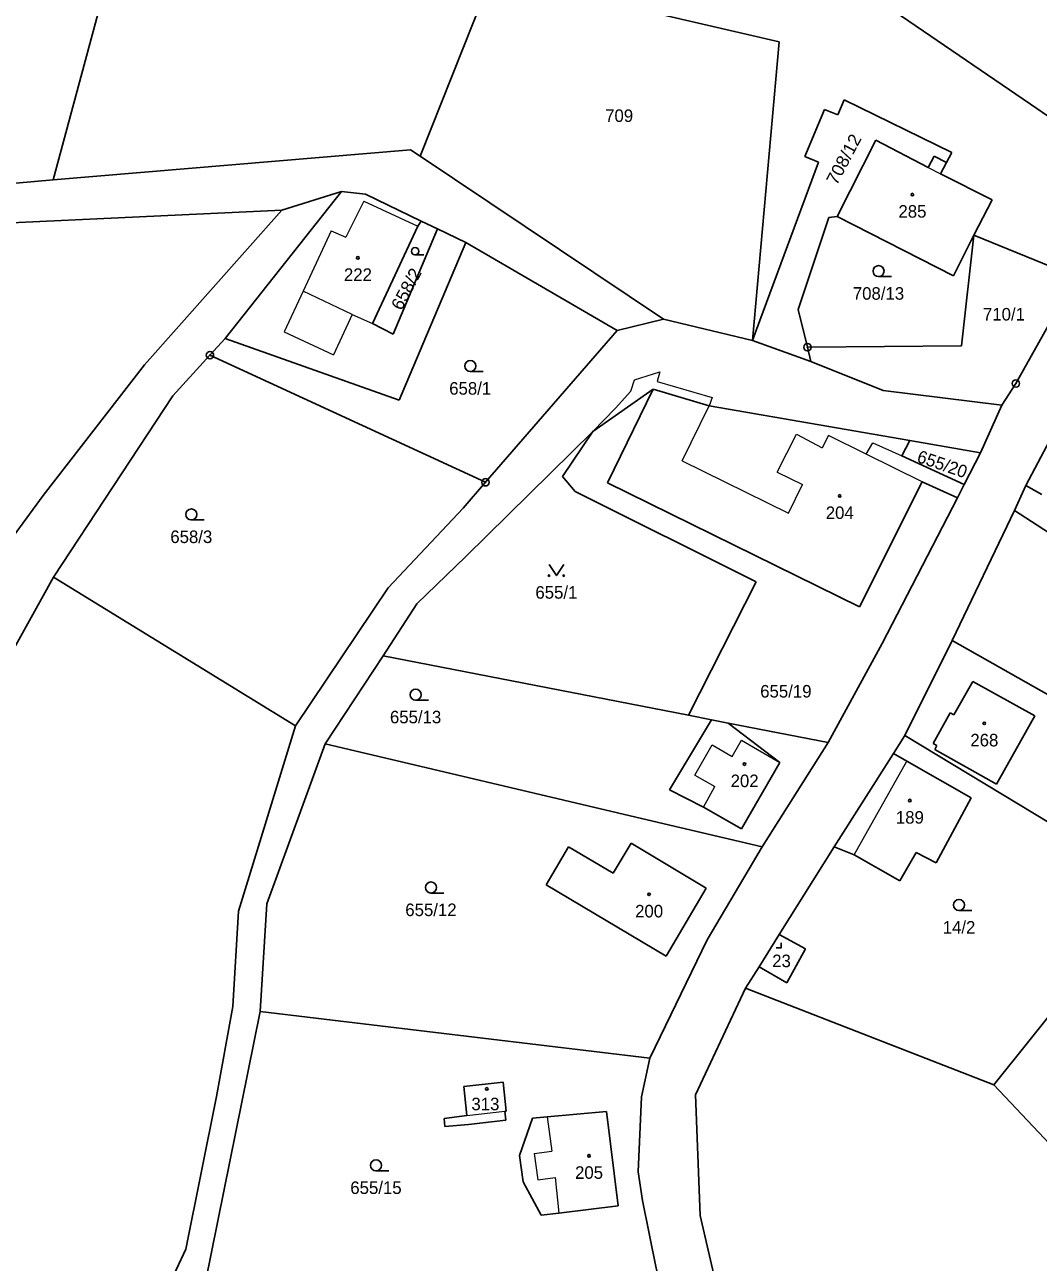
# Model space of a CAD drawing. Extents: x -739410 to -735662, y -942282 to -940043.
# Drawn here: x -738155.3 to -738017.9, y -941607.4 to -941439.7 of the extents above; entities that cross this region are included whole.
import ezdxf
from ezdxf.enums import TextEntityAlignment as Align

# ---------------------------------------------------------------- set-up
doc = ezdxf.new("R2010")
doc.units = 0
doc.header["$LTSCALE"] = 0.68
for name, color, linetype, lineweight in [('1', 7, 'Continuous', 25), ('3', 7, 'Continuous', 25), ('4', 7, 'Continuous', 13), ('5', 7, 'Continuous', 25), ('8', 7, 'Continuous', 25)]:
    doc.layers.add(name, color=color, linetype=linetype, lineweight=lineweight)
doc.layers.add('2', color=7, linetype='Continuous')

msp = doc.modelspace()

# ---------------------------------------------------------------- linework, layer by layer
at = {"layer": '1'}
for p, q in [((-738138.45, -941412.44), (-738151.41, -941460.71)), ((-738101.7, -941457.47), (-738089.41, -941426.65)), ((-738054.59, -941426.11), (-738018.99, -941450.42)), ((-738068.85, -941438.31), (-738053.02, -941441.98)), ((-738053.02, -941441.98), (-738056.64, -941482.45)), ((-738044.24, -941449.83), (-738045.08, -941451.9)), ((-738029.65, -941456.98), (-738044.24, -941449.83)), ((-738046.88, -941451.15), (-738049.56, -941457.51)), ((-738045.08, -941451.9), (-738046.88, -941451.15)), ((-738008.98, -941457.35), (-738018.99, -941450.42)), ((-738045.19, -941465.68), (-738039.95, -941455.33)), ((-738039.95, -941455.33), (-738032.84, -941459.02)), ((-738151.41, -941460.71), (-738102.97, -941456.62)), ((-738102.97, -941456.62), (-738101.7, -941457.47)), ((-738030.35, -941458.33), (-738029.65, -941456.98)), ((-738101.7, -941457.47), (-738068.72, -941479.55)), ((-738047.72, -941458.29), (-738056.09, -941480.97)), ((-738049.56, -941457.51), (-738047.72, -941458.29)), ((-738032.84, -941459.02), (-738032.03, -941457.46)), ((-738032.03, -941457.46), (-738030.35, -941458.33)), ((-738031.16, -941459.89), (-738030.35, -941458.33)), ((-738031.16, -941459.89), (-738024.19, -941463.38)), ((-738164.1, -941461.78), (-738151.41, -941460.71)), ((-738128.12, -941482.21), (-738112.36, -941462.27)), ((-738112.36, -941462.27), (-738120.43, -941464.8)), ((-738109.07, -941462.62), (-738112.36, -941462.27)), ((-738101.54, -941466.27), (-738109.07, -941462.62)), ((-738024.19, -941463.38), (-738026.65, -941468.18)), ((-738120.43, -941464.8), (-738193.39, -941468.24)), ((-738139.04, -941485.78), (-738120.43, -941464.8)), ((-738101.99, -941466.98), (-738108.13, -941480.18)), ((-738101.99, -941466.98), (-738101.54, -941466.27)), ((-738099.31, -941467.35), (-738101.54, -941466.27)), ((-738050.47, -941478.24), (-738046.3, -941465.81)), ((-738046.3, -941465.81), (-738045.19, -941465.68)), ((-738029.43, -941473.68), (-738045.19, -941465.68)), ((-738105.32, -941481.61), (-738099.31, -941467.35)), ((-738095.51, -941469.19), (-738099.31, -941467.35)), ((-738026.65, -941468.18), (-738029.43, -941473.68)), ((-738026.65, -941468.18), (-738028.32, -941483.17)), ((-738014.9, -941472.96), (-738026.65, -941468.18)), ((-738104.51, -941490.55), (-738095.51, -941469.19)), ((-738074.97, -941481.11), (-738095.51, -941469.19)), ((-738013.18, -941474.35), (-738020.96, -941488.3)), ((-738049.21, -941483.38), (-738050.47, -941478.24)), ((-738108.13, -941480.18), (-738105.32, -941481.61)), ((-738068.72, -941479.55), (-738074.97, -941481.11)), ((-738056.64, -941482.45), (-738068.72, -941479.55)), ((-738130.16, -941484.45), (-738128.12, -941482.21)), ((-738128.12, -941482.21), (-738104.51, -941490.55)), ((-738092.82, -941501.68), (-738074.97, -941481.11)), ((-738056.09, -941480.97), (-738056.64, -941482.45)), ((-738048.73, -941485.32), (-738056.64, -941482.45)), ((-738028.32, -941483.17), (-738049.21, -941483.38)), ((-738049.21, -941483.38), (-738048.73, -941485.32)), ((-738135.21, -941489.98), (-738130.16, -941484.45)), ((-738130.16, -941484.45), (-738092.82, -941501.68)), ((-738038.93, -941489.23), (-738048.73, -941485.32)), ((-738152.77, -941503.45), (-738139.04, -941485.78)), ((-738022.86, -941491.24), (-738020.96, -941488.3)), ((-738151.34, -941514.55), (-738135.21, -941489.98)), ((-738078.3, -941494.78), (-738070.1, -941489.06)), ((-738076.3, -941501.77), (-738070.1, -941489.06)), ((-738070.1, -941489.06), (-738062.52, -941491.34)), ((-738022.86, -941491.24), (-738038.93, -941489.23)), ((-738040.29, -941495.14), (-738062.52, -941491.34)), ((-738025.76, -941497.7), (-738022.86, -941491.24)), ((-738014.78, -941492.97), (-738019.6, -941502.11)), ((-738095.49, -941511.76), (-738078.3, -941494.78)), ((-738078.3, -941494.78), (-738082.41, -941500.89)), ((-738035.35, -941496.01), (-738040.29, -941495.14)), ((-738036.43, -941498.11), (-738035.35, -941496.01)), ((-738025.76, -941497.7), (-738035.35, -941496.01)), ((-738036.43, -941498.11), (-738027.95, -941502)), ((-738027.95, -941502), (-738025.76, -941497.7)), ((-738092.82, -941501.68), (-738095.87, -941505.19)), ((-738082.41, -941500.89), (-738080.68, -941502.92)), ((-738076.3, -941501.77), (-738042.14, -941518.57)), ((-738042.14, -941518.57), (-738033.66, -941501.63)), ((-738033.66, -941501.63), (-738028.88, -941503.79)), ((-738028.88, -941503.79), (-738027.95, -941502)), ((-738019.6, -941502.11), (-738021.15, -941505.52)), ((-738017.46, -941503.34), (-738019.6, -941502.11)), ((-738163.68, -941518.34), (-738152.77, -941503.45)), ((-738080.68, -941502.92), (-738056.17, -941515.15)), ((-738039.09, -941523.53), (-738028.88, -941503.79)), ((-738095.87, -941505.19), (-738106.03, -941515.98)), ((-738021.15, -941505.52), (-738029.62, -941523.14)), ((-738021.15, -941505.52), (-738014.09, -941510.1)), ((-738102.14, -941518.16), (-738095.49, -941511.76)), ((-738172.88, -941553.27), (-738151.34, -941514.55)), ((-738151.34, -941514.55), (-738118.55, -941534.68)), ((-738056.17, -941515.15), (-738065.31, -941533.26)), ((-738118.55, -941534.68), (-738106.03, -941515.98)), ((-738106.7, -941525.22), (-738102.14, -941518.16)), ((-738046.38, -941536.96), (-738039.09, -941523.53)), ((-738029.62, -941523.14), (-738035.99, -941536)), ((-738002.21, -941538.58), (-738029.62, -941523.14)), ((-738114.53, -941537.11), (-738106.7, -941525.22)), ((-738065.31, -941533.26), (-738106.7, -941525.22)), ((-738029.37, -941533.19), (-738026.81, -941528.68)), ((-738026.81, -941528.68), (-738018.41, -941533.32)), ((-738062.22, -941533.87), (-738067.88, -941543.34)), ((-738065.31, -941533.26), (-738062.22, -941533.87)), ((-738062.22, -941533.87), (-738059.96, -941534.31)), ((-738032.19, -941537.07), (-738029.85, -941532.92)), ((-738029.85, -941532.92), (-738029.37, -941533.19)), ((-738018.41, -941533.32), (-738023.59, -941542.59)), ((-738126.28, -941559.82), (-738118.55, -941534.68)), ((-738059.96, -941534.31), (-738046.38, -941536.96)), ((-738052.94, -941539.67), (-738059.96, -941534.31)), ((-738122.47, -941558.82), (-738114.53, -941537.11)), ((-738114.53, -941537.11), (-738071.7, -941547.26)), ((-738055.33, -941551.1), (-738046.38, -941536.96)), ((-738035.99, -941536), (-738037.55, -941538.45)), ((-738008.8, -941552.44), (-738035.99, -941536)), ((-738031.67, -941537.37), (-738032.19, -941537.07)), ((-738031.96, -941537.89), (-738031.67, -941537.37)), ((-738037.55, -941538.45), (-738045.58, -941551.1)), ((-738035.75, -941539.48), (-738037.55, -941538.45)), ((-738031.96, -941537.89), (-738023.59, -941542.59)), ((-738058.15, -941548.65), (-738052.94, -941539.67)), ((-738027.04, -941544.44), (-738035.75, -941539.48)), ((-738067.88, -941543.34), (-738063.31, -941545.69)), ((-738063.31, -941545.69), (-738058.15, -941548.65)), ((-738031.77, -941553.27), (-738027.04, -941544.44)), ((-738071.7, -941547.26), (-738055.33, -941551.1)), ((-738075.52, -941554.65), (-738073.1, -941550.57)), ((-738073.1, -941550.57), (-738062.93, -941556.68)), ((-738081.57, -941551.07), (-738084.63, -941556.22)), ((-738075.52, -941554.65), (-738081.57, -941551.07)), ((-738055.33, -941551.1), (-738062.78, -941563.69)), ((-738045.58, -941551.1), (-738053.03, -941562.96)), ((-738045.58, -941551.1), (-738042.87, -941552.15)), ((-738042.87, -941552.15), (-738036.71, -941555.71)), ((-738036.71, -941555.71), (-738034.46, -941551.86)), ((-738034.46, -941551.86), (-738031.77, -941553.27)), ((-738084.63, -941556.22), (-738068.37, -941565.9)), ((-738062.93, -941556.68), (-738068.37, -941565.9)), ((-738023.97, -941583.33), (-738002.35, -941556.34)), ((-738123.35, -941573.41), (-738122.47, -941558.82)), ((-738127.06, -941572.75), (-738126.28, -941559.82)), ((-738062.78, -941563.69), (-738070.55, -941579.75)), ((-738053.03, -941562.96), (-738055.77, -941567.33)), ((-738053.03, -941562.96), (-738049.46, -941564.9)), ((-738052.01, -941569.53), (-738049.46, -941564.9)), ((-738055.77, -941567.33), (-738057.6, -941570.24)), ((-738052.01, -941569.53), (-738055.77, -941567.33)), ((-738064.38, -941584.68), (-738057.6, -941570.24)), ((-738057.6, -941570.24), (-738023.97, -941583.33)), ((-738129.27, -941584.94), (-738127.06, -941572.75)), ((-738130.76, -941610.06), (-738123.35, -941573.41)), ((-738123.35, -941573.41), (-738070.55, -941579.75)), ((-738070.55, -941579.75), (-738071.7, -941584.97)), ((-738095.78, -941583.57), (-738090.44, -941582.99)), ((-738095.35, -941587.5), (-738095.78, -941583.57)), ((-738090.44, -941582.99), (-738090.03, -941586.9)), ((-738004.7, -941603.8), (-738023.97, -941583.33)), ((-738133.45, -941605.62), (-738129.27, -941584.94)), ((-738071.7, -941584.97), (-738072.12, -941595.14)), ((-738063.74, -941601.06), (-738064.38, -941584.68)), ((-738098.45, -941587.89), (-738095.35, -941587.5)), ((-738098.35, -941589.01), (-738098.45, -941587.89)), ((-738090.03, -941586.9), (-738090.23, -941586.92)), ((-738090.23, -941586.92), (-738090.07, -941588.15)), ((-738088.2, -941592.92), (-738086.44, -941587.85)), ((-738084.45, -941587.67), (-738086.44, -941587.85)), ((-738076.44, -941586.95), (-738084.45, -941587.67)), ((-738076.44, -941586.95), (-738074.86, -941599.73)), ((-738095.13, -941588.73), (-738098.35, -941589.01)), ((-738090.07, -941588.15), (-738095.13, -941588.73)), ((-738088.2, -941592.92), (-738087.72, -941596.49)), ((-738072.12, -941595.14), (-738071.57, -941599.04)), ((-738085.27, -941601.03), (-738087.72, -941596.49)), ((-738082.88, -941600.74), (-738085.27, -941601.03)), ((-738074.86, -941599.73), (-738082.88, -941600.74)), ((-738055.94, -941635.06), (-738063.74, -941601.06)), ((-738144.51, -941629.21), (-738133.45, -941605.62))]:
    msp.add_line(p, q, dxfattribs=at)
msp.add_lwpolyline([(-738071.57, -941599.04), (-738069.69, -941608.19), (-738068.56, -941612.67)], dxfattribs=at)
at = {"layer": '3'}
for p, q in [((-738102.365, -941470.87), (-738101.193, -941470.87)), ((-738039.573, -941473.81), (-738037.823, -941473.81)), ((-738094.893, -941486.68), (-738093.143, -941486.68)), ((-738132.683, -941506.79), (-738130.933, -941506.79)), ((-738102.293, -941531.22), (-738100.543, -941531.22)), ((-738100.213, -941557.35), (-738098.463, -941557.35)), ((-738028.663, -941559.72), (-738026.913, -941559.72)), ((-738107.663, -941595.01), (-738105.913, -941595.01))]:
    msp.add_line(p, q, dxfattribs=at)
for points in [[(-738084.22, -941512.829), (-738083.22, -941514.33), (-738082.22, -941512.829)], [(-738053.431, -941564.76), (-738052.76, -941564.76), (-738052.76, -941564.09)]]:
    msp.add_lwpolyline(points, dxfattribs=at)
for centre, radius in [((-738102.3652, -941470.3674), 0.5025), ((-738039.5729, -941473.0598), 0.75), ((-738094.8929, -941485.9298), 0.75), ((-738132.6829, -941506.0398), 0.75), ((-738084.22, -941514.3295), 0.1), ((-738082.22, -941514.3295), 0.1), ((-738102.2929, -941530.4698), 0.75), ((-738100.2129, -941556.5998), 0.75), ((-738028.6629, -941558.9698), 0.75), ((-738107.6629, -941594.2598), 0.75)]:
    msp.add_circle(centre, radius, dxfattribs=at)
at = {"layer": '4'}
for p, q in [((-738032.84, -941459.02), (-738031.16, -941459.89)), ((-738109.31, -941463.56), (-738111.74, -941468.47)), ((-738109.31, -941463.56), (-738101.99, -941466.98)), ((-738113.76, -941467.61), (-738117.55, -941475.79)), ((-738113.76, -941467.61), (-738111.74, -941468.47)), ((-738117.55, -941475.79), (-738120.1, -941481.31)), ((-738110.88, -941478.94), (-738117.55, -941475.79)), ((-738110.88, -941478.94), (-738113.42, -941484.39)), ((-738110.88, -941478.94), (-738108.13, -941480.18)), ((-738120.1, -941481.31), (-738113.42, -941484.39)), ((-738072.66, -941487.78), (-738069.19, -941486.7)), ((-738069.19, -941486.7), (-738069.58, -941488.01)), ((-738073.12, -941489.31), (-738072.66, -941487.78)), ((-738069.58, -941488.01), (-738062.13, -941490.21)), ((-738075.21, -941491.63), (-738073.12, -941489.31)), ((-738062.13, -941490.21), (-738062.52, -941491.34)), ((-738078.3, -941494.78), (-738075.21, -941491.63)), ((-738066.2, -941498.78), (-738062.52, -941491.34)), ((-738053.29, -941500.31), (-738050.69, -941495.17)), ((-738050.69, -941495.17), (-738047.23, -941497.02)), ((-738046.34, -941495.36), (-738047.23, -941497.02)), ((-738041.23, -941497.89), (-738046.34, -941495.36)), ((-738041.23, -941497.89), (-738040.33, -941496.32)), ((-738040.33, -941496.32), (-738036.43, -941498.11)), ((-738066.2, -941498.78), (-738051.79, -941505.87)), ((-738033.66, -941501.63), (-738041.23, -941497.89)), ((-738053.29, -941500.31), (-738049.86, -941502)), ((-738051.79, -941505.87), (-738049.86, -941502)), ((-738064.47, -941541.37), (-738062.1, -941537.28)), ((-738062.1, -941537.28), (-738059.39, -941538.84)), ((-738059.39, -941538.84), (-738058.15, -941536.62)), ((-738058.15, -941536.62), (-738052.94, -941539.67)), ((-738042.87, -941552.15), (-738035.75, -941539.48)), ((-738064.47, -941541.37), (-738061.76, -941542.92)), ((-738063.31, -941545.69), (-738061.76, -941542.92)), ((-738095.35, -941587.5), (-738090.23, -941586.92)), ((-738084.45, -941587.67), (-738083.84, -941592.33)), ((-738086.22, -941592.64), (-738083.84, -941592.33)), ((-738086.22, -941592.64), (-738085.75, -941596.21)), ((-738085.75, -941596.21), (-738083.37, -941595.9)), ((-738083.37, -941595.9), (-738082.88, -941600.74))]:
    msp.add_line(p, q, dxfattribs=at)
at = {"layer": '5'}
for centre in [(-738034.9868, -941462.6892), (-738110.1168, -941471.2592), (-738044.8368, -941503.5292), (-738025.2468, -941534.3492), (-738057.7268, -941539.8692), (-738035.3368, -941544.8192), (-738070.6668, -941557.5292), (-738092.6568, -941583.8992), (-738078.8068, -941592.9592)]:
    msp.add_circle(centre, 0.175, dxfattribs=at)
at = {"layer": '8'}
for centre, radius in [((-738049.21, -941483.3799), 0.5), ((-738049.21, -941483.3799), 0.0303), ((-738130.16, -941484.4499), 0.5), ((-738130.16, -941484.4499), 0.0303), ((-738020.96, -941488.2999), 0.5), ((-738020.96, -941488.2999), 0.0303), ((-738092.82, -941501.6799), 0.5), ((-738092.82, -941501.6799), 0.0303)]:
    msp.add_circle(centre, radius, dxfattribs=at)

# ---------------------------------------------------------------- texts
at = {"layer": '2'}
for s, p in [('709', (-738074.719, -941452.845)), ('285', (-738034.979, -941465.815)), ('222', (-738110.109, -941474.385)), ('708/13', (-738039.58, -941476.935)), ('710/1', (-738022.58, -941479.755)), ('658/1', (-738094.9, -941489.805)), ('204', (-738044.829, -941506.655)), ('658/3', (-738132.69, -941509.915)), ('655/1', (-738083.22, -941517.455)), ('655/19', (-738052.13, -941530.855)), ('655/13', (-738102.3, -941534.345)), ('268', (-738025.239, -941537.475)), ('202', (-738057.719, -941542.995)), ('189', (-738035.329, -941547.945)), ('655/12', (-738100.22, -941560.475)), ('200', (-738070.659, -941560.655)), ('14/2', (-738028.669, -941562.845)), ('23', (-738052.719, -941567.395)), ('313', (-738092.839, -941586.785)), ('205', (-738078.799, -941596.085)), ('655/15', (-738107.67, -941598.135))]:
    msp.add_text(s, height=1.7, dxfattribs=at).set_placement(p, align=Align.CENTER)
at = {"layer": '2', "width": 1.05}
for s, p in [('708/12', (-738043.5265, -941458.2961)), ('658/2', (-738102.8064, -941475.8756))]:
    msp.add_text(s, height=1.7, rotation=62, dxfattribs=at).set_placement(p, align=Align.CENTER)
at = {"layer": '2'}
msp.add_text('655/20', height=1.7, rotation=341, dxfattribs=at).set_placement((-738031.2067, -941500.02), align=Align.CENTER)

doc.saveas('drawing.dxf')
